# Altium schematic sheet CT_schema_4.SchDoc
size 211 x 163 mm
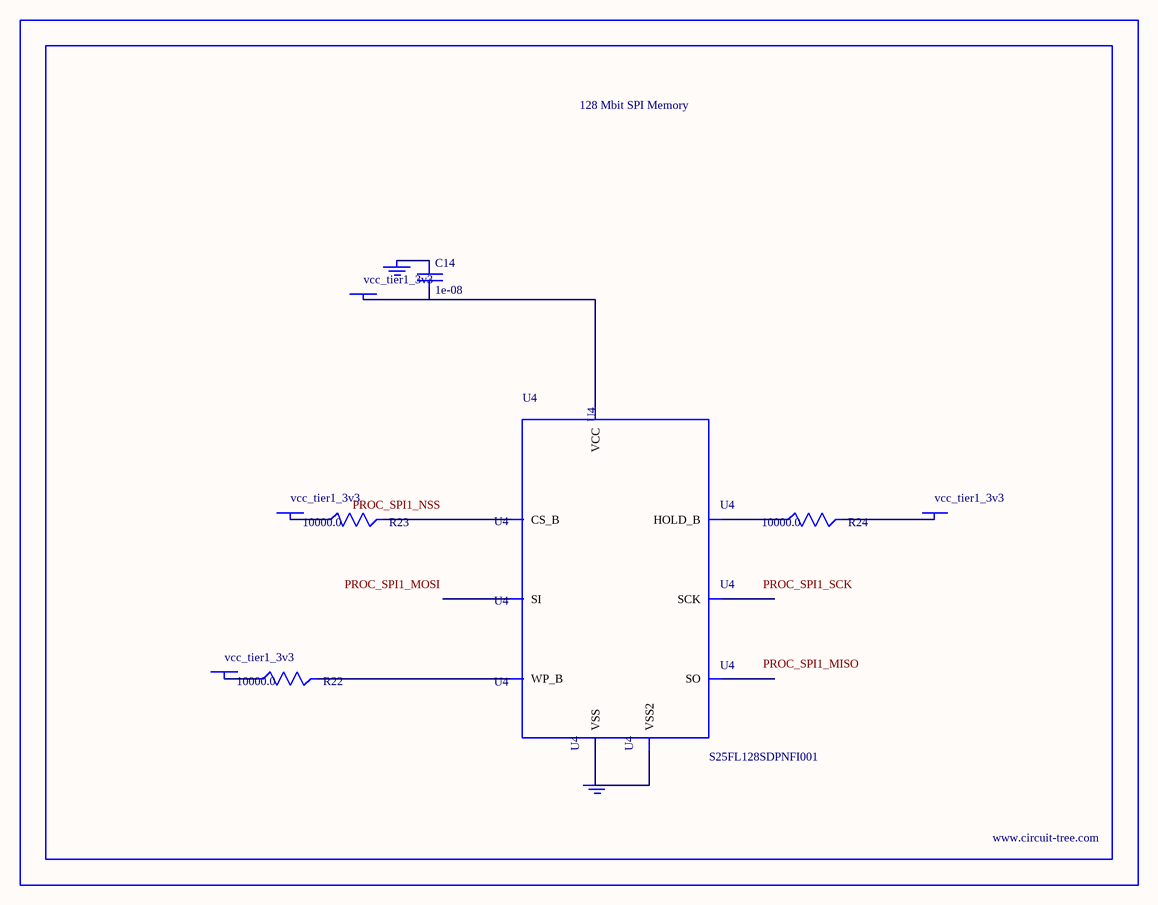
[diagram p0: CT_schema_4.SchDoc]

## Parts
BORDER3  (no value)
C14  1e-08  [C0402]
GND_INSTANCE_3_0  (no value)
GND_INSTANCE_3_1  (no value)
POWER_INSTANCE_3_0  vcc_tier1_3v3
POWER_INSTANCE_3_1  vcc_tier1_3v3
POWER_INSTANCE_3_2  vcc_tier1_3v3
POWER_INSTANCE_3_3  vcc_tier1_3v3
R22  10000.0  [R0603]
R23  10000.0  [R0603]
R24  10000.0  [R0603]
U4  S25FL128SDPNFI001  [WNG008]

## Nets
NetC14_1: C14.1 GND_INSTANCE_3_0.0(GND)
NetC14_2: C14.2 POWER_INSTANCE_3_3.0(PWR) U4.8(VCC)
NetGND_INSTANCE_3_1_0: GND_INSTANCE_3_1.0(GND) U4.4(VSS) U4.PAD(VSS2)
NetPOWER_INSTANCE_3_0_0: POWER_INSTANCE_3_0.0(PWR) R23.1
NetPOWER_INSTANCE_3_1_0: POWER_INSTANCE_3_1.0(PWR) R22.1
NetPOWER_INSTANCE_3_2_0: POWER_INSTANCE_3_2.0(PWR) R24.2
NetR22_2: R22.2 U4.3(WP_B)
NetR23_2: R23.2 U4.1(CS_B)
NetR24_1: R24.1 U4.7(HOLD_B)

Not connected (* = marked no-connect by the designer): U4 2(SO) 5(SI) 6(SCK)

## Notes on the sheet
- Labels drawn without touching a wire or pin: PROC_SPI1_MISO, PROC_SPI1_MOSI, PROC_SPI1_NSS, PROC_SPI1_SCK

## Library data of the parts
BORDER3 = BORDER_PAGE3
C14 = C0402C103K3RAC
GND_INSTANCE_3_0 GND_INSTANCE_3_1 = GND
POWER_INSTANCE_3_0-POWER_INSTANCE_3_3 = PWR
R22-R24 = RC0603JR-0710KL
